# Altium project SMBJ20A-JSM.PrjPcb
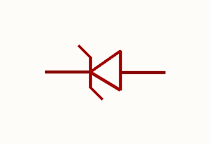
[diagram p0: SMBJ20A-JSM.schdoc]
1 sheet, 1 parts. Net scope: global (net labels, ports and power ports of the same name join across sheets).

## Sheet SMBJ20A-JSM.schdoc
size 127 x 101 mm

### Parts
D?  smbj20a-jsm  [SMB_L4.6-W3.6-LS5.3-RD]  (value not drawn)

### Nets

Not connected (* = marked no-connect by the designer): D? 1(C) 2(A)

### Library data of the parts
D? = smbj20a-jsm: 极性:单向;反向截止电压(Vrwm):20V;钳位电压:32.4V;峰值脉冲电流(Ipp):18.6A;峰值脉冲功率(Ppp):600W;击穿电压(VBR):24.5V;; Manufacturer: JSMSEMI(杰盛微); AddInBom: yes; ModelId: 5e8926c661484ff2a35b83e5ae62aeb9; ModelTransform: 212.598,141.732,0,0,0,0,0,0,0; Polarity: 单向; Reverse Stand-Off Voltage (Vrwm): 20V; Clamping Voltage: 32.4V; Peak Pulse Current (Ipp): 18.6A; Peak Pulse Power Dissipation (Ppp): 600W; Voltage - Breakdown: 24.5V; Reverse Leakage Current (Ir): 1uA; Number of Channels: 单路; Type: TVS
